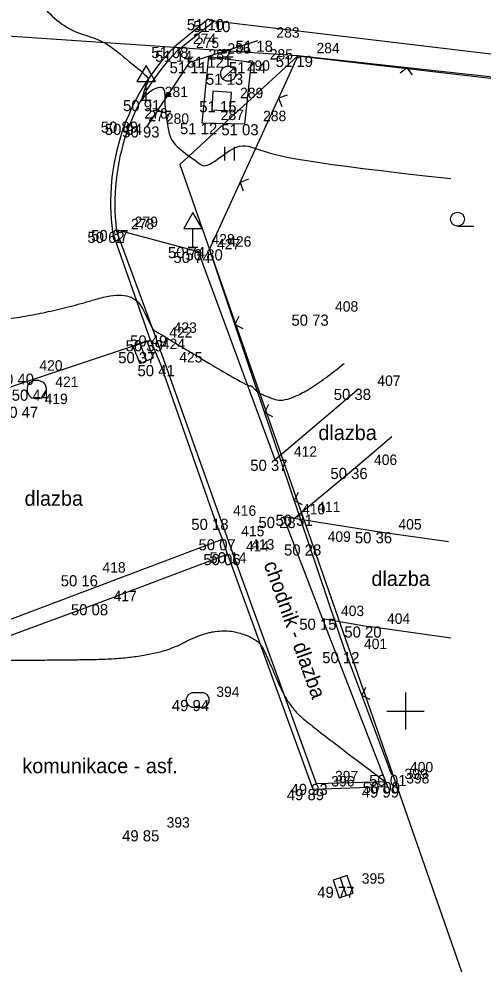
# Model space of a CAD drawing. Extents: x -704057 to -703795, y -1008732 to -1008584.
# Drawn here: x -703985.42 to -703972.91, y -1008681.82 to -1008656.35 of the extents above; entities that cross this region are included whole.
import ezdxf

# ---------------------------------------------------------------- set-up
doc = ezdxf.new("R2010")
doc.units = 0
for name, color, linetype in [('Z_body', 7, 'Continuous'), ('Z_body_cisla', 7, 'Continuous'), ('Z_body_vysky', 7, 'Continuous'), ('Z_chodnik', 7, 'Continuous'), ('Z_dopravni_znaceni', 7, 'Continuous'), ('Z_hekt_sit', 7, 'Continuous'), ('Z_katastr_hranice', 7, 'Continuous'), ('Z_komunikace_zpevn_pl', 7, 'Continuous'), ('Z_obruby', 7, 'Continuous'), ('Z_oploceni', 7, 'Continuous'), ('Z_popis', 7, 'Continuous'), ('Z_rozhrani_zpevn', 7, 'Continuous'), ('Z_site_znaky_kanalizace', 7, 'Continuous'), ('Z_site_znaky_plyn', 7, 'Continuous'), ('Z_site_znaky_vodovod', 7, 'Continuous'), ('Z_vrstevnice_hlavni', 7, 'Continuous'), ('Z_vrstevnice_popis', 7, 'Continuous'), ('Z_vrstevnice_vedlejsi', 7, 'Continuous'), ('Z_vstupy', 7, 'Continuous'), ('Z_zabradli', 7, 'Continuous')]:
    doc.layers.add(name, color=color, linetype=linetype)

# ---------------------------------------------------------------- blocks, each defined once
blk = doc.blocks.new('POINT_DISPLAY')
blk.add_line((0, 0), (0, 0))
blk = doc.blocks.new('Z212')
for p, q in [((-0.17, 0.17), (0, 0)), ((0, 0), (0.17, 0.17))]:
    blk.add_line(p, q)
blk = doc.blocks.new('Z530')
for p, q in [((-0.05, 0.03), (-0.03, 0.05)), ((-0.05, -0.03), (-0.05, 0.03)), ((-0.03, 0.05), (0.03, 0.05)), ((-0.03, -0.03), (-0.03, 0.03)), ((-0.03, 0.03), (0.03, 0.03)), ((-0.03, -0.03), (0.03, 0.03)), ((0.03, 0.05), (0.05, 0.03)), ((0.03, 0.03), (0.03, -0.03)), ((0.05, 0.03), (0.05, -0.03)), ((-0.03, -0.05), (-0.05, -0.03)), ((0.03, -0.03), (-0.03, -0.03)), ((0.03, -0.05), (-0.03, -0.05)), ((0.05, -0.03), (0.03, -0.05))]:
    blk.add_line(p, q)
blk = doc.blocks.new('Z620')
for p, q in [((-0.25, 0.05), (-0.23, 0.13)), ((-0.25, -0.05), (-0.25, 0.05)), ((-0.23, 0.13), (-0.17, 0.2)), ((-0.17, 0.2), (-0.05, 0.25)), ((-0.05, 0.25), (0.05, 0.25)), ((0.05, 0.25), (0.17, 0.2)), ((0.17, 0.2), (0.23, 0.13)), ((0.23, 0.13), (0.25, 0.05)), ((0.25, 0.05), (0.25, -0.05)), ((-0.2, -0.17), (-0.25, -0.05)), ((-0.13, -0.23), (-0.2, -0.17)), ((-0.05, -0.25), (-0.13, -0.23)), ((0.05, -0.25), (-0.05, -0.25)), ((0.13, -0.23), (0.05, -0.25)), ((0.2, -0.17), (0.13, -0.23)), ((0.25, -0.05), (0.2, -0.17))]:
    blk.add_line(p, q)
blk = doc.blocks.new('Z38')
for p, q in [((0.25, 0.2), (-0.25, 0.2)), ((-0.25, 0.2), (-0.25, -0.2)), ((-0.25, 0), (0.25, 0)), ((0.25, -0.2), (0.25, 0.2)), ((-0.25, -0.2), (0.25, -0.2))]:
    blk.add_line(p, q)
blk = doc.blocks.new('Z18')
for p, q in [((-0.13, 0.45), (0.13, 0.45)), ((0, 0.2), (0, 0.45)), ((-0.2, 0.05), (-0.15, 0.15)), ((-0.2, -0.05), (-0.2, 0.05)), ((-0.15, 0.15), (-0.05, 0.2)), ((0.15, 0.15), (-0.15, -0.15)), ((-0.05, 0.2), (0.05, 0.2)), ((0.05, 0.2), (0.15, 0.15)), ((0.15, 0.15), (0.2, 0.05)), ((0.2, 0.05), (0.2, -0.05)), ((-0.15, -0.15), (-0.2, -0.05)), ((-0.05, -0.2), (-0.15, -0.15)), ((0.05, -0.2), (-0.05, -0.2)), ((0.15, -0.15), (0.05, -0.2)), ((0.2, -0.05), (0.15, -0.15))]:
    blk.add_line(p, q)
blk = doc.blocks.new('Z608')
for p, q in [((0.25, 0.25), (-0.25, 0.25)), ((-0.25, 0.25), (-0.25, -0.25)), ((0.25, -0.25), (0.25, 0.25)), ((-0.25, -0.25), (0.25, -0.25))]:
    blk.add_line(p, q)
blk = doc.blocks.new('Z14')
for p, q in [((-0.3, 0.05), (-0.25, 0.15)), ((-0.3, -0.05), (-0.3, 0.05)), ((-0.25, 0.15), (-0.15, 0.2)), ((-0.15, 0.2), (0.15, 0.2)), ((0.15, 0.2), (0.25, 0.15)), ((0.25, 0.15), (0.3, 0.05)), ((0.3, 0.05), (0.3, -0.05)), ((-0.25, -0.15), (-0.3, -0.05)), ((-0.15, -0.2), (-0.25, -0.15)), ((0.15, -0.2), (-0.15, -0.2)), ((0.25, -0.15), (0.15, -0.2)), ((0.3, -0.05), (0.25, -0.15))]:
    blk.add_line(p, q)
blk = doc.blocks.new('Z527')
for p, q in [((0, 0.93), (-0.25, 0.5)), ((0.25, 0.5), (0, 0.93)), ((-0.25, 0.5), (0.25, 0.5)), ((0, 0), (0, 0.5)), ((-0.13, 0), (0.13, 0))]:
    blk.add_line(p, q)
blk = doc.blocks.new('Z306')
for p, q in [((-0.13, 0.17), (-0.13, -0.2)), ((0.13, 0.17), (0.13, -0.2))]:
    blk.add_line(p, q)
blk = doc.blocks.new('Z304')
blk.add_line((0, -0.19), (0.44, -0.19))
blk.add_circle((0, 0), 0.188)

msp = doc.modelspace()

# ---------------------------------------------------------------- linework, layer by layer
at = {"layer": 'Z_chodnik'}
for p, q in [((-703980.58, -1008662.63), (-703982.8, -1008662.04)), ((-703978.51, -1008668.23), (-703980.58, -1008662.63)), ((-703976.26, -1008666.32), (-703978.51, -1008668.23)), ((-703975.37, -1008667.61), (-703976.35, -1008668.45)), ((-703976.35, -1008668.45), (-703977.88, -1008669.71)), ((-703977.24, -1008672.51), (-703978.29, -1008669.77)), ((-703975.69, -1008670.18), (-703978.29, -1008669.77)), ((-703977.88, -1008669.71), (-703978, -1008669.82)), ((-703973.84, -1008670.44), (-703975.69, -1008670.18)), ((-703975.53, -1008676.91), (-703977.24, -1008672.51)), ((-703977.24, -1008672.51), (-703976, -1008672.72)), ((-703973.78, -1008673.04), (-703976, -1008672.72)), ((-703975.48, -1008677.03), (-703975.53, -1008676.91))]:
    msp.add_line(p, q, dxfattribs=at)
at = {"layer": 'Z_hekt_sit'}
for p, q in [((-703975, -1008674.5), (-703975, -1008675.5)), ((-703975.5, -1008675), (-703974.5, -1008675))]:
    msp.add_line(p, q, dxfattribs=at)
at = {"layer": 'Z_katastr_hranice'}
for p, q in [((-703977.9, -1008657.35), (-703986.13, -1008656.79)), ((-703977.9, -1008657.35), (-703981.08, -1008660.28)), ((-703977.9, -1008657.35), (-703947.65, -1008660.85)), ((-703981.08, -1008660.28), (-703970.86, -1008689.54))]:
    msp.add_line(p, q, dxfattribs=at)
at = {"layer": 'Z_komunikace_zpevn_pl'}
for p, q in [((-703980.32, -1008656.36), (-703981.23, -1008657.11)), ((-703980.32, -1008656.36), (-703980.15, -1008656.41)), ((-703980.15, -1008656.41), (-703971.14, -1008657.48)), ((-703981.87, -1008665.01), (-703982.9, -1008662.09)), ((-703981.87, -1008665.01), (-703981.6, -1008665.68)), ((-703981.6, -1008665.68), (-703980.15, -1008669.82)), ((-703979.93, -1008670.37), (-703980.15, -1008669.82)), ((-703979.8, -1008670.77), (-703979.93, -1008670.37)), ((-703979.8, -1008670.77), (-703977.5, -1008677.1)), ((-703977.5, -1008677.1), (-703975.48, -1008677.03))]:
    msp.add_line(p, q, dxfattribs=at)
msp.add_arc((-703977, -1008661.3), 5.952, 135.2788, 187.6443, dxfattribs=at)
at = {"layer": 'Z_obruby'}
for p, q in [((-703981.15, -1008657.21), (-703980.15, -1008656.41)), ((-703981.75, -1008664.88), (-703982.8, -1008662.04)), ((-703979.66, -1008670.72), (-703981.75, -1008664.88)), ((-703977.4, -1008676.96), (-703979.66, -1008670.72)), ((-703975.53, -1008676.91), (-703977.4, -1008676.96))]:
    msp.add_line(p, q, dxfattribs=at)
msp.add_arc((-703976.94, -1008661.34), 5.897, 135.4969, 186.7813, dxfattribs=at)
at = {"layer": 'Z_oploceni'}
for p, q in [((-703977.9, -1008657.35), (-703980.28, -1008662.56)), ((-703971.23, -1008658.08), (-703977.9, -1008657.35)), ((-703977.6, -1008670.51), (-703980.28, -1008662.56)), ((-703976.62, -1008673.41), (-703975.38, -1008676.72))]:
    msp.add_line(p, q, dxfattribs=at)
at = {"layer": 'Z_rozhrani_zpevn'}
for p, q in [((-703980.48, -1008659.16), (-703980.3, -1008657.37)), ((-703980.3, -1008657.37), (-703979.16, -1008657.52)), ((-703979.16, -1008657.52), (-703979.34, -1008659.19)), ((-703979.34, -1008659.19), (-703980.48, -1008659.16)), ((-703989.18, -1008667.44), (-703981.87, -1008665.01)), ((-703987.03, -1008673.05), (-703979.93, -1008670.37)), ((-703983.37, -1008672.12), (-703979.8, -1008670.77)), ((-703986.88, -1008673.41), (-703983.37, -1008672.12))]:
    msp.add_line(p, q, dxfattribs=at)
at = {"layer": 'Z_vrstevnice_hlavni'}
msp.add_open_spline([(-703986.743, -1008674.608), (-703986.74, -1008674.61), (-703986.737, -1008674.589), (-703986.81, -1008673.6), (-703986.889, -1008673.432), (-703986.955, -1008673.23), (-703986.49, -1008673.267), (-703986.81, -1008673.6), (-703985.37, -1008673.634), (-703985.333, -1008673.63), (-703981.787, -1008673.594), (-703980.2, -1008672.735), (-703978.988, -1008673.004), (-703978.692, -1008673.627), (-703978.153, -1008674.88), (-703977.349, -1008675.544), (-703975.53, -1008676.91)], degree=2, dxfattribs=at)
at = {"layer": 'Z_vrstevnice_popis'}
msp.add_open_spline([(-703985.231, -1008654.773), (-703985.233, -1008654.99), (-703985.209, -1008655.538), (-703984.22, -1008656.692), (-703983.2, -1008656.858), (-703982.505, -1008657.462), (-703981.889, -1008657.948), (-703981.945, -1008658.047), (-703982.027, -1008658.206), (-703982.128, -1008658.577), (-703982.119, -1008658.578), (-703981.97, -1008658.325), (-703981.459, -1008658.081), (-703981.513, -1008658.577), (-703981.415, -1008659.217), (-703981.332, -1008659.732), (-703980.559, -1008660.215), (-703980.405, -1008660.435), (-703979.463, -1008659.63), (-703979.059, -1008659.888), (-703977.693, -1008660.229), (-703973.778, -1008660.657)], degree=3, dxfattribs=at)
at = {"layer": 'Z_vrstevnice_vedlejsi'}
msp.add_open_spline([(-703991.305, -1008666.866), (-703990.71, -1008667.458), (-703989.91, -1008666.842), (-703989.702, -1008666.469), (-703990.341, -1008664.544), (-703990.478, -1008664.084), (-703990.202, -1008664.369), (-703990.172, -1008664.089), (-703988.378, -1008664.725), (-703985.803, -1008664.468), (-703984.247, -1008664.174), (-703982.363, -1008663.613), (-703981.838, -1008664.665), (-703981.808, -1008664.722), (-703981.703, -1008664.79), (-703979.237, -1008666.262), (-703979.164, -1008666.207), (-703978.967, -1008666.455), (-703978.04, -1008666.762), (-703976.651, -1008665.634)], degree=2, dxfattribs=at)
at = {"layer": 'Z_vstupy'}
msp.add_line((-703976.62, -1008673.41), (-703977.6, -1008670.51), dxfattribs=at)
at = {"layer": 'Z_zabradli'}
for p, q in [((-703980.81, -1008657.52), (-703978.98, -1008656.94)), ((-703981.96, -1008659.25), (-703980.81, -1008657.52))]:
    msp.add_line(p, q, dxfattribs=at)

# ---------------------------------------------------------------- block references
at = {"layer": 'Z_body'}
for p in [(-703980.32, -1008656.36), (-703980.15, -1008656.41), (-703978.98, -1008656.94), (-703981.23, -1008657.11), (-703981.15, -1008657.21), (-703980.3, -1008657.37), (-703977.9, -1008657.35), (-703980.81, -1008657.52), (-703979.16, -1008657.52), (-703979.78, -1008657.83), (-703981.99, -1008658.54), (-703979.96, -1008658.57), (-703982.54, -1008659.12), (-703982.43, -1008659.18), (-703980.48, -1008659.16), (-703979.34, -1008659.19), (-703981.96, -1008659.25), (-703982.9, -1008662.09), (-703982.8, -1008662.04), (-703980.73, -1008662.5), (-703980.58, -1008662.63), (-703980.28, -1008662.56), (-703977.4, -1008664.32), (-703981.87, -1008665.01), (-703981.75, -1008664.88), (-703982.07, -1008665.33), (-703981.6, -1008665.68), (-703985.37, -1008665.91), (-703984.94, -1008666.34), (-703976.26, -1008666.32), (-703985.23, -1008666.8), (-703978.51, -1008668.23), (-703976.35, -1008668.45), (-703980.15, -1008669.82), (-703978.29, -1008669.77), (-703977.88, -1008669.71), (-703975.69, -1008670.18), (-703979.93, -1008670.37), (-703977.6, -1008670.51), (-703979.8, -1008670.77), (-703979.66, -1008670.72), (-703983.67, -1008671.34), (-703983.37, -1008672.12), (-703977.24, -1008672.51), (-703976, -1008672.72), (-703976.62, -1008673.41), (-703980.6, -1008674.7), (-703975.38, -1008676.72), (-703977.4, -1008676.96), (-703975.53, -1008676.91), (-703975.48, -1008677.03), (-703977.5, -1008677.1), (-703981.94, -1008678.21), (-703976.68, -1008679.73)]:
    msp.add_blockref('POINT_DISPLAY', p, dxfattribs=at)
at = {"layer": 'Z_dopravni_znaceni'}
for p in [(-703981.99, -1008658.54), (-703980.73, -1008662.5)]:
    msp.add_blockref('Z527', p, dxfattribs=at)
at = {"layer": 'Z_oploceni'}
for p, rotation in [((-703974.96, -1008657.67), 173.8), ((-703978.42, -1008658.49), -114.60000000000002), ((-703979.46, -1008660.76), -114.60000000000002), ((-703979.6, -1008664.59), -71.4), ((-703978.8, -1008666.96), -71.4), ((-703978, -1008669.33), -71.4), ((-703976.18, -1008674.58), -69.50000000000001)]:
    msp.add_blockref('Z212', p, dxfattribs=dict(at, rotation=rotation))
at = {"layer": 'Z_popis'}
for name, p in [('Z306', (-703979.75, -1008659.97)), ('Z304', (-703973.6, -1008661.75))]:
    msp.add_blockref(name, p, dxfattribs=at)
at = {"layer": 'Z_site_znaky_kanalizace'}
for p, rotation in [((-703982.07, -1008665.33), -68.39999999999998), ((-703976.68, -1008679.73), -71.10000000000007)]:
    msp.add_blockref('Z38', p, dxfattribs=dict(at, rotation=rotation))
msp.add_blockref('Z620', (-703984.94, -1008666.34), dxfattribs=at)
at = {"layer": 'Z_site_znaky_plyn'}
msp.add_blockref('Z14', (-703980.6, -1008674.7), dxfattribs=at)
at = {"layer": 'Z_site_znaky_vodovod'}
msp.add_blockref('Z18', (-703979.78, -1008657.83), dxfattribs=at)
at = {"layer": 'Z_site_znaky_vodovod', "rotation": -3.599999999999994}
msp.add_blockref('Z608', (-703979.96, -1008658.57), dxfattribs=at)
at = {"layer": 'Z_zabradli'}
for p, rotation in [((-703979.89, -1008657.23), 17.599999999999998), ((-703981.39, -1008658.39), -123.60000000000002)]:
    msp.add_blockref('Z530', p, dxfattribs=dict(at, rotation=rotation))

# ---------------------------------------------------------------- texts
at = {"layer": 'Z_body_cisla'}
for s, p in [('283', (-703978.48, -1008656.86)), ('274', (-703980.73, -1008657.03)), ('275', (-703980.65, -1008657.14)), ('282', (-703980.31, -1008657.45)), ('286', (-703979.8, -1008657.29)), ('285', (-703978.66, -1008657.45)), ('284', (-703977.4, -1008657.28)), ('290', (-703979.28, -1008657.75)), ('281', (-703981.49, -1008658.46)), ('289', (-703979.46, -1008658.49)), ('276', (-703982.04, -1008659.04)), ('277', (-703981.93, -1008659.11)), ('280', (-703981.46, -1008659.18)), ('287', (-703979.98, -1008659.08)), ('288', (-703978.84, -1008659.11)), ('278', (-703982.4, -1008662.02)), ('279', (-703982.3, -1008661.96)), ('428', (-703980.23, -1008662.43)), ('427', (-703980.08, -1008662.56)), ('426', (-703979.78, -1008662.49)), ('408', (-703976.9, -1008664.24)), ('423', (-703981.25, -1008664.81)), ('422', (-703981.37, -1008664.94)), ('424', (-703981.57, -1008665.25)), ('425', (-703981.1, -1008665.61)), ('420', (-703984.87, -1008665.83)), ('421', (-703984.44, -1008666.27)), ('407', (-703975.76, -1008666.24)), ('419', (-703984.73, -1008666.73)), ('412', (-703978.01, -1008668.15)), ('406', (-703975.85, -1008668.37)), ('410', (-703977.79, -1008669.7)), ('411', (-703977.38, -1008669.64)), ('416', (-703979.65, -1008669.74)), ('405', (-703975.19, -1008670.11)), ('415', (-703979.43, -1008670.29)), ('409', (-703977.1, -1008670.44)), ('414', (-703979.3, -1008670.7)), ('413', (-703979.16, -1008670.65)), ('418', (-703983.17, -1008671.27)), ('417', (-703982.87, -1008672.04)), ('403', (-703976.74, -1008672.44)), ('404', (-703975.5, -1008672.65)), ('401', (-703976.12, -1008673.33)), ('394', (-703980.1, -1008674.62)), ('399', (-703975.03, -1008676.83)), ('400', (-703974.88, -1008676.65)), ('396', (-703977, -1008677.03)), ('397', (-703976.9, -1008676.89)), ('398', (-703974.98, -1008676.95)), ('393', (-703981.44, -1008678.14)), ('395', (-703976.18, -1008679.65))]:
    msp.add_text(s, height=0.28, dxfattribs=at).set_placement(p)
at = {"layer": 'Z_body_vysky'}
for s, p in [('51 10', (-703980.895, -1008656.66)), ('51 10', (-703980.725, -1008656.71)), ('51 18', (-703979.58, -1008657.24)), ('51 08', (-703981.855, -1008657.41)), ('51 14', (-703981.75, -1008657.51)), ('51 12', (-703980.9, -1008657.67)), ('51 19', (-703978.5, -1008657.65)), ('51 11', (-703981.36, -1008657.82)), ('51 14', (-703979.76, -1008657.82)), ('51 13', (-703980.38, -1008658.13)), ('50 91', (-703982.615, -1008658.84)), ('51 15', (-703980.56, -1008658.87)), ('50 89', (-703983.215, -1008659.42)), ('50 94', (-703983.105, -1008659.48)), ('51 12', (-703981.08, -1008659.46)), ('51 03', (-703979.965, -1008659.49)), ('50 93', (-703982.635, -1008659.55)), ('50 62', (-703983.575, -1008662.39)), ('50 67', (-703983.475, -1008662.34)), ('50 74', (-703981.405, -1008662.8)), ('50 74', (-703981.255, -1008662.93)), ('50 80', (-703980.93, -1008662.86)), ('50 73', (-703978.075, -1008664.62)), ('50 39', (-703982.545, -1008665.31)), ('50 49', (-703982.425, -1008665.18)), ('50 37', (-703982.745, -1008665.63)), ('50 41', (-703982.225, -1008665.98)), ('50 40', (-703986.02, -1008666.21)), ('50 44', (-703985.615, -1008666.64)), ('50 38', (-703976.935, -1008666.62)), ('50 47', (-703985.905, -1008667.1)), ('50 37', (-703979.185, -1008668.53)), ('50 36', (-703977.025, -1008668.75)), ('50 18', (-703980.775, -1008670.12)), ('50 28', (-703978.965, -1008670.07)), ('50 31', (-703978.505, -1008670.01)), ('50 36', (-703976.365, -1008670.48)), ('50 07', (-703980.58, -1008670.67)), ('50 28', (-703978.275, -1008670.81)), ('50 06', (-703980.45, -1008671.07)), ('50 14', (-703980.285, -1008671.02)), ('50 16', (-703984.295, -1008671.64)), ('50 08', (-703984.02, -1008672.42)), ('50 15', (-703977.865, -1008672.81)), ('50 20', (-703976.65, -1008673.02)), ('50 12', (-703977.245, -1008673.71)), ('49 94', (-703981.3, -1008675)), ('50 01', (-703975.98, -1008677.02)), ('49 93', (-703978.1, -1008677.26)), ('49 99', (-703976.18, -1008677.33)), ('50 00', (-703976.155, -1008677.21)), ('49 89', (-703978.2, -1008677.4)), ('49 85', (-703982.64, -1008678.51)), ('49 77', (-703977.38, -1008680.03))]:
    msp.add_text(s, height=0.3, dxfattribs=at).set_placement(p)
at = {"layer": 'Z_popis'}
for s, p in [('dlazba', (-703977.35, -1008667.7)), ('dlazba', (-703985.27, -1008669.47)), ('dlazba', (-703975.92, -1008671.63)), ('komunikace - asf.', (-703985.33, -1008676.674))]:
    msp.add_text(s, height=0.4, dxfattribs=at).set_placement(p)
msp.add_text('chodnik - dlazba', height=0.4, rotation=289.8, dxfattribs=at).set_placement((-703978.83, -1008671.04))

doc.saveas('drawing.dxf')
